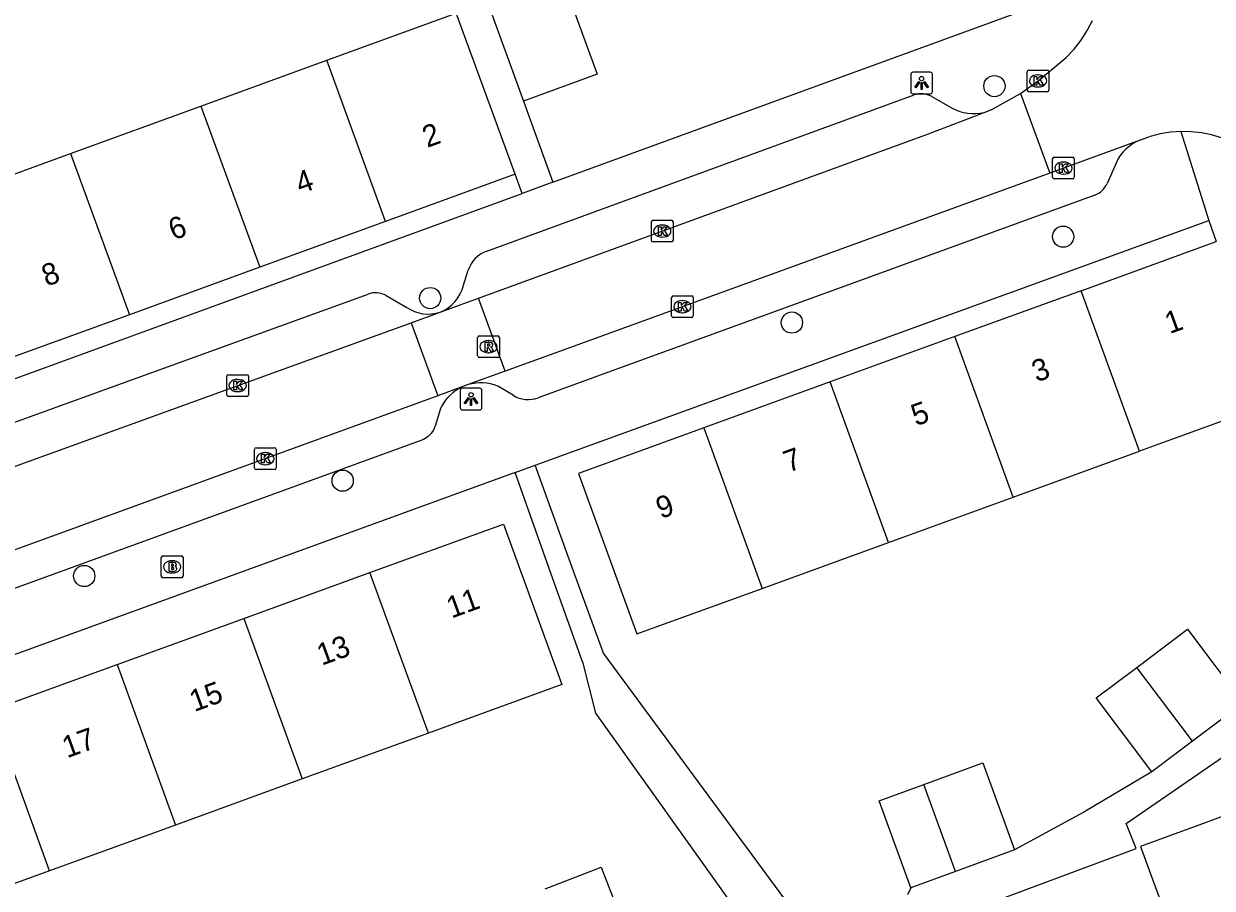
# Model space of a CAD drawing. Extents: x 159222 to 160346, y 381249 to 382166.
# Drawn here: x 159605.3 to 159660.1, y 381397.6 to 381437.5 of the extents above; entities that cross this region are included whole.
import ezdxf

# ---------------------------------------------------------------- set-up
doc = ezdxf.new("R2010")
doc.units = 0
for name, color, linetype in [('IMGEO_Boom', 7, 'Continuous'), ('IMGEO_Brandkraan', 7, 'Continuous'), ('IMGEO_Kolk', 7, 'Continuous'), ('IMGEO_Lichtpunt', 7, 'Continuous'), ('IMGEO_Pand', 7, 'Continuous'), ('IMGEO_Pand_nummerreeks', 7, 'Continuous'), ('IMGEO_Rijbaan_lokaal_open', 7, 'Continuous'), ('IMGEO_Rioolput', 7, 'Continuous'), ('IMGEO_Voetpad_open', 7, 'Continuous')]:
    doc.layers.add(name, color=color, linetype=linetype)

msp = doc.modelspace()

# ---------------------------------------------------------------- linework, layer by layer
at = {"layer": 'IMGEO_Boom'}
for centre in [(159650.085, 381434.629), (159653.252, 381427.689), (159624.075, 381424.855), (159640.749, 381423.725), (159620.038, 381416.439), (159608.128, 381412.043)]:
    msp.add_circle(centre, 0.489, dxfattribs=at)
at = {"layer": 'IMGEO_Brandkraan'}
for p, q in [((159611.679, 381412.038), (159611.679, 381412.89)), ((159611.754, 381412.964), (159612.606, 381412.964)), ((159612.167, 381412.744), (159612.192, 381412.744)), ((159612.68, 381412.89), (159612.68, 381412.038)), ((159612.19, 381412.184), (159612.165, 381412.184)), ((159612.606, 381411.964), (159611.754, 381411.964))]:
    msp.add_line(p, q, dxfattribs=at)
for points in [[(159611.679, 381412.038), (159611.679, 381412.89)], [(159611.754, 381412.964), (159612.606, 381412.964)], [(159612.68, 381412.89), (159612.68, 381412.038)], [(159612.027, 381412.664), (159612.027, 381412.264), (159612.24, 381412.264)], [(159612.258, 381412.664), (159612.027, 381412.664)], [(159612.206, 381412.583), (159612.152, 381412.583), (159612.152, 381412.507)], [(159612.152, 381412.507), (159612.205, 381412.507)], [(159612.214, 381412.431), (159612.152, 381412.431), (159612.152, 381412.35)], [(159612.152, 381412.35), (159612.214, 381412.35)], [(159612.606, 381411.964), (159611.754, 381411.964)]]:
    msp.add_lwpolyline(points, dxfattribs=at)
for centre, radius, start, end in [((159611.756, 381412.888), 0.0765, 91.552, 178.448), ((159611.756, 381412.888), 0.0765, 91.552, 178.448), ((159612.604, 381412.888), 0.0765, 1.552, 88.448), ((159612.604, 381412.888), 0.0765, 1.552, 88.448), ((159612.207, 381412.545), 0.0379, 267.8285, 90.9355), ((159612.215, 381412.39), 0.0404, 269.8759, 90.5077), ((159612.246, 381412.515), 0.251, 268.6676, 293.5347), ((159612.262, 381412.519), 0.145, 59.4692, 91.5367), ((159612.287, 381412.566), 0.0922, 285.5137, 58.1501), ((159612.292, 381412.374), 0.105, 301.3115, 78.989), ((159611.756, 381412.04), 0.0765, 181.552, 268.448), ((159611.756, 381412.04), 0.0765, 181.552, 268.448), ((159612.604, 381412.04), 0.0765, 271.552, 358.448), ((159612.604, 381412.04), 0.0765, 271.552, 358.448)]:
    msp.add_arc(centre, radius, start, end, dxfattribs=at)
for centre, major_axis, ratio, start_param, end_param in [((159612.166, 381412.464), (-0.387, 0.002), 0.722429, 4.712389, 7.853982), ((159612.191, 381412.464), (-0.39, 0.002), 0.717154, 1.570796, 4.712389)]:
    msp.add_ellipse(centre, major_axis=major_axis, ratio=ratio, start_param=start_param, end_param=end_param, dxfattribs=at)
at = {"layer": 'IMGEO_Kolk'}
for p, q in [((159651.596, 381434.442), (159651.596, 381435.294)), ((159651.671, 381435.368), (159652.523, 381435.368)), ((159652.597, 381435.294), (159652.597, 381434.442)), ((159652.084, 381435.148), (159652.109, 381435.148)), ((159652.523, 381434.368), (159651.671, 381434.368)), ((159652.107, 381434.588), (159652.082, 381434.588)), ((159652.766, 381430.424), (159652.766, 381431.276)), ((159652.841, 381431.35), (159653.693, 381431.35)), ((159653.254, 381431.13), (159653.279, 381431.13)), ((159653.767, 381431.276), (159653.767, 381430.424)), ((159653.693, 381430.35), (159652.841, 381430.35)), ((159653.277, 381430.57), (159653.252, 381430.57)), ((159634.273, 381427.518), (159634.273, 381428.37)), ((159634.348, 381428.444), (159635.2, 381428.444)), ((159634.761, 381428.224), (159634.786, 381428.224)), ((159635.274, 381428.37), (159635.274, 381427.518)), ((159634.784, 381427.664), (159634.759, 381427.664)), ((159635.2, 381427.444), (159634.348, 381427.444)), ((159635.202, 381424.032), (159635.202, 381424.884)), ((159635.277, 381424.958), (159636.129, 381424.958)), ((159636.203, 381424.884), (159636.203, 381424.032)), ((159635.69, 381424.738), (159635.715, 381424.738)), ((159636.129, 381423.958), (159635.277, 381423.958)), ((159635.713, 381424.178), (159635.688, 381424.178)), ((159614.699, 381420.398), (159614.699, 381421.25)), ((159614.774, 381421.324), (159615.626, 381421.324)), ((159615.187, 381421.104), (159615.212, 381421.104)), ((159615.7, 381421.25), (159615.7, 381420.398)), ((159615.21, 381420.544), (159615.185, 381420.544)), ((159615.626, 381420.324), (159614.774, 381420.324)), ((159615.974, 381417.027), (159615.974, 381417.879)), ((159616.049, 381417.953), (159616.901, 381417.953)), ((159616.462, 381417.733), (159616.487, 381417.733)), ((159616.975, 381417.879), (159616.975, 381417.027)), ((159616.485, 381417.173), (159616.46, 381417.173)), ((159616.901, 381416.953), (159616.049, 381416.953))]:
    msp.add_line(p, q, dxfattribs=at)
for points in [[(159651.596, 381434.442), (159651.596, 381435.294)], [(159651.671, 381435.368), (159652.523, 381435.368)], [(159652.597, 381435.294), (159652.597, 381434.442)], [(159651.917, 381435.068), (159652.04, 381435.068), (159652.04, 381434.917), (159652.17, 381435.068), (159652.334, 381435.068), (159652.188, 381434.917), (159652.341, 381434.668), (159652.189, 381434.668), (159652.104, 381434.832), (159652.04, 381434.765), (159652.04, 381434.668), (159651.917, 381434.668), (159651.917, 381435.068)], [(159652.523, 381434.368), (159651.671, 381434.368)], [(159652.766, 381430.424), (159652.766, 381431.276)], [(159652.841, 381431.35), (159653.693, 381431.35)], [(159653.087, 381431.05), (159653.21, 381431.05), (159653.21, 381430.899), (159653.34, 381431.05), (159653.504, 381431.05), (159653.358, 381430.899), (159653.511, 381430.65), (159653.359, 381430.65), (159653.274, 381430.814), (159653.21, 381430.747), (159653.21, 381430.65), (159653.087, 381430.65), (159653.087, 381431.05)], [(159653.767, 381431.276), (159653.767, 381430.424)], [(159653.693, 381430.35), (159652.841, 381430.35)], [(159634.273, 381427.518), (159634.273, 381428.37)], [(159634.348, 381428.444), (159635.2, 381428.444)], [(159634.594, 381428.144), (159634.717, 381428.144), (159634.717, 381427.993), (159634.847, 381428.144), (159635.011, 381428.144), (159634.865, 381427.993), (159635.018, 381427.744), (159634.866, 381427.744), (159634.781, 381427.908), (159634.717, 381427.841), (159634.717, 381427.744), (159634.594, 381427.744), (159634.594, 381428.144)], [(159635.274, 381428.37), (159635.274, 381427.518)], [(159635.2, 381427.444), (159634.348, 381427.444)], [(159635.202, 381424.032), (159635.202, 381424.884)], [(159635.277, 381424.958), (159636.129, 381424.958)], [(159636.203, 381424.884), (159636.203, 381424.032)], [(159635.523, 381424.658), (159635.646, 381424.658), (159635.646, 381424.507), (159635.776, 381424.658), (159635.94, 381424.658), (159635.794, 381424.507), (159635.947, 381424.258), (159635.795, 381424.258), (159635.71, 381424.422), (159635.646, 381424.355), (159635.646, 381424.258), (159635.523, 381424.258), (159635.523, 381424.658)], [(159636.129, 381423.958), (159635.277, 381423.958)], [(159614.699, 381420.398), (159614.699, 381421.25)], [(159614.774, 381421.324), (159615.626, 381421.324)], [(159615.02, 381421.024), (159615.143, 381421.024), (159615.143, 381420.873), (159615.273, 381421.024), (159615.437, 381421.024), (159615.291, 381420.873), (159615.444, 381420.624), (159615.292, 381420.624), (159615.207, 381420.788), (159615.143, 381420.721), (159615.143, 381420.624), (159615.02, 381420.624), (159615.02, 381421.024)], [(159615.7, 381421.25), (159615.7, 381420.398)], [(159615.626, 381420.324), (159614.774, 381420.324)], [(159615.974, 381417.027), (159615.974, 381417.879)], [(159616.049, 381417.953), (159616.901, 381417.953)], [(159616.975, 381417.879), (159616.975, 381417.027)], [(159616.295, 381417.653), (159616.418, 381417.653), (159616.418, 381417.502), (159616.548, 381417.653), (159616.712, 381417.653), (159616.566, 381417.502), (159616.719, 381417.253), (159616.567, 381417.253), (159616.482, 381417.417), (159616.418, 381417.35), (159616.418, 381417.253), (159616.295, 381417.253), (159616.295, 381417.653)], [(159616.901, 381416.953), (159616.049, 381416.953)]]:
    msp.add_lwpolyline(points, dxfattribs=at)
for centre, start, end in [((159651.673, 381435.292), 91.552, 178.448), ((159651.673, 381435.292), 91.552, 178.448), ((159652.521, 381435.292), 1.552, 88.448), ((159652.521, 381435.292), 1.552, 88.448), ((159651.673, 381434.444), 181.552, 268.448), ((159651.673, 381434.444), 181.552, 268.448), ((159652.521, 381434.444), 271.552, 358.448), ((159652.521, 381434.444), 271.552, 358.448), ((159652.843, 381431.274), 91.552, 178.448), ((159652.843, 381431.274), 91.552, 178.448), ((159653.691, 381431.274), 1.552, 88.448), ((159653.691, 381431.274), 1.552, 88.448), ((159652.843, 381430.426), 181.552, 268.448), ((159652.843, 381430.426), 181.552, 268.448), ((159653.691, 381430.426), 271.552, 358.448), ((159653.691, 381430.426), 271.552, 358.448), ((159634.35, 381428.368), 91.552, 178.448), ((159634.35, 381428.368), 91.552, 178.448), ((159635.198, 381428.368), 1.552, 88.448), ((159635.198, 381428.368), 1.552, 88.448), ((159634.35, 381427.52), 181.552, 268.448), ((159634.35, 381427.52), 181.552, 268.448), ((159635.198, 381427.52), 271.552, 358.448), ((159635.198, 381427.52), 271.552, 358.448), ((159635.279, 381424.882), 91.552, 178.448), ((159635.279, 381424.882), 91.552, 178.448), ((159636.127, 381424.882), 1.552, 88.448), ((159636.127, 381424.882), 1.552, 88.448), ((159635.279, 381424.034), 181.552, 268.448), ((159635.279, 381424.034), 181.552, 268.448), ((159636.127, 381424.034), 271.552, 358.448), ((159636.127, 381424.034), 271.552, 358.448), ((159614.776, 381421.248), 91.552, 178.448), ((159614.776, 381421.248), 91.552, 178.448), ((159615.624, 381421.248), 1.552, 88.448), ((159615.624, 381421.248), 1.552, 88.448), ((159614.776, 381420.4), 181.552, 268.448), ((159614.776, 381420.4), 181.552, 268.448), ((159615.624, 381420.4), 271.552, 358.448), ((159615.624, 381420.4), 271.552, 358.448), ((159616.051, 381417.877), 91.552, 178.448), ((159616.051, 381417.877), 91.552, 178.448), ((159616.899, 381417.877), 1.552, 88.448), ((159616.899, 381417.877), 1.552, 88.448), ((159616.051, 381417.029), 181.552, 268.448), ((159616.051, 381417.029), 181.552, 268.448), ((159616.899, 381417.029), 271.552, 358.448), ((159616.899, 381417.029), 271.552, 358.448)]:
    msp.add_arc(centre, 0.0765, start, end, dxfattribs=at)
for centre, major_axis, ratio, start_param, end_param in [((159652.083, 381434.868), (-0.387, 0.002), 0.722429, 4.712389, 7.853982), ((159652.108, 381434.868), (-0.39, 0.002), 0.717154, 1.570796, 4.712389), ((159653.253, 381430.85), (-0.387, 0.002), 0.722429, 4.712389, 7.853982), ((159653.278, 381430.85), (-0.39, 0.002), 0.717154, 1.570796, 4.712389), ((159634.76, 381427.944), (-0.387, 0.002), 0.722429, 4.712389, 7.853982), ((159634.785, 381427.944), (-0.39, 0.002), 0.717154, 1.570796, 4.712389), ((159635.689, 381424.458), (-0.387, 0.002), 0.722429, 4.712389, 7.853982), ((159635.714, 381424.458), (-0.39, 0.002), 0.717154, 1.570796, 4.712389), ((159615.186, 381420.824), (-0.387, 0.002), 0.722429, 4.712389, 7.853982), ((159615.211, 381420.824), (-0.39, 0.002), 0.717154, 1.570796, 4.712389), ((159616.461, 381417.453), (-0.387, 0.002), 0.722429, 4.712389, 7.853982), ((159616.486, 381417.453), (-0.39, 0.002), 0.717154, 1.570796, 4.712389)]:
    msp.add_ellipse(centre, major_axis=major_axis, ratio=ratio, start_param=start_param, end_param=end_param, dxfattribs=at)
at = {"layer": 'IMGEO_Lichtpunt'}
for p, q in [((159647.132, 381435.271), (159646.324, 381435.271)), ((159647.132, 381435.271), (159646.324, 381435.271)), ((159646.23, 381435.176), (159646.23, 381434.369)), ((159646.23, 381435.176), (159646.23, 381434.369)), ((159647.226, 381434.369), (159647.226, 381435.176)), ((159647.226, 381434.369), (159647.226, 381435.176)), ((159646.324, 381434.275), (159647.132, 381434.275)), ((159646.324, 381434.275), (159647.132, 381434.275)), ((159625.46, 381420.602), (159625.46, 381419.795)), ((159625.46, 381420.602), (159625.46, 381419.795)), ((159626.362, 381420.697), (159625.554, 381420.697)), ((159626.362, 381420.697), (159625.554, 381420.697)), ((159626.456, 381419.795), (159626.456, 381420.602)), ((159626.456, 381419.795), (159626.456, 381420.602)), ((159625.554, 381419.701), (159626.362, 381419.701)), ((159625.554, 381419.701), (159626.362, 381419.701))]:
    msp.add_line(p, q, dxfattribs=at)
for points in [[(159646.604, 381434.84), (159646.643, 381434.812), (159646.455, 381434.55), (159646.417, 381434.577), (159646.604, 381434.84)], [(159646.706, 381434.792), (159646.753, 381434.792), (159646.753, 381434.47), (159646.706, 381434.47), (159646.706, 381434.792)], [(159646.816, 381434.812), (159646.854, 381434.839), (159647.041, 381434.577), (159647.002, 381434.549), (159646.816, 381434.812)], [(159625.834, 381420.266), (159625.873, 381420.238), (159625.685, 381419.976), (159625.647, 381420.003), (159625.834, 381420.266)], [(159625.936, 381420.218), (159625.983, 381420.218), (159625.983, 381419.896), (159625.936, 381419.896), (159625.936, 381420.218)], [(159626.046, 381420.238), (159626.084, 381420.265), (159626.271, 381420.003), (159626.232, 381419.975), (159626.046, 381420.238)]]:
    msp.add_lwpolyline(points, dxfattribs=at)
for centre in [(159646.729, 381434.974), (159625.959, 381420.4)]:
    msp.add_circle(centre, 0.0994, dxfattribs=at)
for centre, start, end in [((159646.324, 381435.176), 90, 180), ((159646.324, 381435.176), 90, 180), ((159647.132, 381435.176), 0, 90), ((159647.132, 381435.176), 0, 90), ((159646.324, 381434.369), 180, 270), ((159646.324, 381434.369), 180, 270), ((159647.132, 381434.369), 270, 0), ((159647.132, 381434.369), 270, 360), ((159625.554, 381420.602), 90, 180), ((159625.554, 381420.602), 90, 180), ((159626.362, 381420.602), 0, 90), ((159626.362, 381420.602), 0, 90), ((159625.554, 381419.795), 180, 270), ((159625.554, 381419.795), 180, 270), ((159626.362, 381419.795), 270, 0), ((159626.362, 381419.795), 270, 360)]:
    msp.add_arc(centre, 0.0946, start, end, dxfattribs=at)
at = {"layer": 'IMGEO_Pand'}
for points in [[(159626.725, 381438.45), (159630.125, 381439.69), (159631.77, 381435.176), (159628.37, 381433.937)], [(159619.309, 381435.822), (159625.278, 381437.998)], [(159627.986, 381430.569), (159626.274, 381435.267), (159625.278, 381437.998)], [(159626.725, 381438.45), (159628.37, 381433.937)], [(159613.506, 381433.706), (159619.309, 381435.822)], [(159622.018, 381428.393), (159619.309, 381435.822)], [(159607.501, 381431.517), (159613.506, 381433.706)], [(159613.506, 381433.706), (159616.215, 381426.278)], [(159601.858, 381429.46), (159607.501, 381431.517)], [(159607.501, 381431.517), (159610.21, 381424.089)], [(159627.986, 381430.569), (159622.018, 381428.393)], [(159622.018, 381428.393), (159616.215, 381426.278)], [(159654.081, 381425.197), (159660.305, 381427.46)], [(159616.215, 381426.278), (159610.21, 381424.089)], [(159654.081, 381425.197), (159648.254, 381423.079)], [(159656.772, 381417.793), (159654.081, 381425.197)], [(159610.21, 381424.089), (159604.567, 381422.032)], [(159648.254, 381423.079), (159642.509, 381420.991)], [(159650.946, 381415.675), (159648.254, 381423.079)], [(159642.509, 381420.991), (159636.683, 381418.872)], [(159645.201, 381413.587), (159642.509, 381420.991)], [(159662.997, 381420.056), (159658.298, 381418.348), (159656.772, 381417.793)], [(159636.683, 381418.872), (159630.905, 381416.772), (159632.613, 381412.073), (159633.596, 381409.368), (159639.374, 381411.469)], [(159636.683, 381418.872), (159639.374, 381411.469)], [(159650.946, 381415.675), (159656.772, 381417.793)], [(159645.201, 381413.587), (159650.946, 381415.675)], [(159621.299, 381412.201), (159627.45, 381414.437), (159629.159, 381409.739), (159630.142, 381407.035), (159623.99, 381404.798)], [(159639.374, 381411.469), (159645.201, 381413.587)], [(159615.485, 381410.087), (159621.299, 381412.201)], [(159623.99, 381404.798), (159621.299, 381412.201)], [(159609.644, 381407.964), (159615.485, 381410.087)], [(159615.485, 381410.087), (159618.176, 381402.685)], [(159656.644, 381407.827), (159658.991, 381409.59), (159661.552, 381406.18)], [(159603.835, 381405.852), (159609.644, 381407.964)], [(159609.644, 381407.964), (159612.335, 381400.561)], [(159657.335, 381403.012), (159654.773, 381406.421), (159656.644, 381407.827)], [(159659.215, 381404.424), (159656.644, 381407.827)], [(159661.552, 381406.18), (159659.215, 381404.424)], [(159606.526, 381398.449), (159603.835, 381405.852)], [(159623.99, 381404.798), (159618.176, 381402.685)], [(159659.215, 381404.424), (159657.335, 381403.012)], [(159646.829, 381402.425), (159649.556, 381403.42), (159651.017, 381399.415)], [(159670.828, 381398.23), (159669.904, 381400.754), (159668.351, 381400.186), (159667.19, 381403.357), (159662.471, 381401.643), (159659.05, 381400.391), (159656.814, 381399.573), (159658.904, 381393.862), (159661.14, 381394.681)], [(159618.176, 381402.685), (159612.335, 381400.561)], [(159646.229, 381397.668), (159644.767, 381401.673), (159646.829, 381402.425)], [(159648.288, 381398.419), (159646.829, 381402.425)], [(159612.335, 381400.561), (159606.526, 381398.449)], [(159651.017, 381399.415), (159648.288, 381398.419)], [(159629.368, 381397.623), (159631.949, 381398.621), (159633.519, 381394.563)], [(159606.526, 381398.449), (159600.648, 381396.312)], [(159648.288, 381398.419), (159646.229, 381397.668)]]:
    msp.add_lwpolyline(points, dxfattribs=at)
at = {"layer": 'IMGEO_Rijbaan_lokaal_open'}
for points in [[(159651.291, 381434.293), (159652.095, 381434.865), (159653.397, 381435.95), (159653.755, 381436.334), (159654.077, 381436.749), (159654.361, 381437.191), (159654.605, 381437.657)], [(159649.608, 381433.413), (159649.962, 381433.555), (159651.291, 381434.293)], [(159651.291, 381434.293), (159652.632, 381430.621)], [(159626.306, 381424.852), (159647.045, 381432.423), (159649.608, 381433.413)], [(159658.676, 381432.534), (159658.2, 381432.499), (159657.73, 381432.422), (159657.268, 381432.304), (159657.185, 381432.278), (159656.809, 381432.141)], [(159663.908, 381429.84), (159663.482, 381430.34), (159663.013, 381430.8), (159662.505, 381431.216), (159662.429, 381431.272), (159661.945, 381431.597), (159661.433, 381431.877), (159660.995, 381432.073), (159660.551, 381432.248), (159660.094, 381432.382), (159659.626, 381432.475), (159659.152, 381432.525), (159658.676, 381432.534)], [(159656.809, 381432.141), (159652.632, 381430.621)], [(159652.632, 381430.621), (159631.043, 381422.764), (159627.533, 381421.485)], [(159624.535, 381424.208), (159625.459, 381424.543), (159626.306, 381424.852)], [(159627.533, 381421.485), (159626.306, 381424.852)], [(159589.053, 381411.283), (159601.832, 381415.978), (159623.195, 381423.722)], [(159623.195, 381423.722), (159624.535, 381424.208)], [(159623.195, 381423.722), (159624.423, 381420.352)], [(159627.533, 381421.485), (159625.829, 381420.864)], [(159625.581, 381420.773), (159624.423, 381420.352)], [(159625.829, 381420.864), (159625.581, 381420.773)], [(159624.423, 381420.352), (159602.469, 381412.351), (159590.271, 381407.929)]]:
    msp.add_lwpolyline(points, dxfattribs=at)
at = {"layer": 'IMGEO_Rioolput'}
for p, q in [((159626.263, 381422.187), (159626.263, 381423.039)), ((159626.338, 381423.113), (159627.19, 381423.113)), ((159626.751, 381422.893), (159626.776, 381422.893)), ((159627.264, 381423.039), (159627.264, 381422.187)), ((159627.19, 381422.113), (159626.338, 381422.113)), ((159626.774, 381422.333), (159626.749, 381422.333))]:
    msp.add_line(p, q, dxfattribs=at)
for points in [[(159626.263, 381422.187), (159626.263, 381423.039)], [(159626.338, 381423.113), (159627.19, 381423.113)], [(159626.852, 381422.811), (159626.6, 381422.813), (159626.6, 381422.413)], [(159626.778, 381422.732), (159626.724, 381422.732), (159626.724, 381422.651)], [(159626.724, 381422.651), (159626.776, 381422.651)], [(159627.264, 381423.039), (159627.264, 381422.187)], [(159627.19, 381422.113), (159626.338, 381422.113)], [(159626.6, 381422.413), (159626.724, 381422.413), (159626.724, 381422.575), (159626.735, 381422.575)], [(159626.782, 381422.546), (159626.853, 381422.413), (159626.993, 381422.413), (159626.928, 381422.539)]]:
    msp.add_lwpolyline(points, dxfattribs=at)
for centre, radius, start, end in [((159626.34, 381423.037), 0.0765, 91.552, 178.448), ((159626.34, 381423.037), 0.0765, 91.552, 178.448), ((159626.76, 381422.84), 0.19, 274.7715, 282.9687), ((159626.784, 381422.636), 0.0964, 77.0061, 93.1865), ((159626.798, 381422.693), 0.0378, 276.6634, 79.6772), ((159626.851, 381422.701), 0.109, 350.3612, 89.416), ((159626.849, 381422.701), 0.112, 277.5842, 350.9817), ((159627.188, 381423.037), 0.0765, 1.552, 88.448), ((159627.188, 381423.037), 0.0765, 1.552, 88.448), ((159626.34, 381422.189), 0.0765, 181.552, 268.448), ((159626.34, 381422.189), 0.0765, 181.552, 268.448), ((159626.734, 381422.522), 0.0533, 26.0293, 88.6989), ((159626.833, 381422.486), 0.108, 29.5134, 73.7905), ((159627.188, 381422.189), 0.0765, 271.552, 358.448), ((159627.188, 381422.189), 0.0765, 271.552, 358.448)]:
    msp.add_arc(centre, radius, start, end, dxfattribs=at)
for centre, major_axis, ratio, start_param, end_param in [((159626.75, 381422.613), (-0.387, 0.002), 0.722429, 4.712389, 7.853982), ((159626.775, 381422.613), (-0.39, 0.002), 0.717154, 1.570796, 4.712389)]:
    msp.add_ellipse(centre, major_axis=major_axis, ratio=ratio, start_param=start_param, end_param=end_param, dxfattribs=at)
at = {"layer": 'IMGEO_Voetpad_open'}
for points in [[(159629.734, 381430.203), (159651.161, 381438.028), (159651.846, 381438.493), (159652.201, 381439.407), (159652.095, 381440.154), (159651.623, 381441.001)], [(159626.679, 381427.026), (159646.388, 381434.221)], [(159647.192, 381434.146), (159648.139, 381433.618)], [(159628.37, 381433.937), (159629.734, 381430.203)], [(159658.676, 381432.534), (159659.964, 381428.438)], [(159655.691, 381431.076), (159655.28, 381430.14)], [(159628.31, 381429.683), (159627.986, 381430.569)], [(159629.734, 381430.203), (159628.31, 381429.683)], [(159555.602, 381403.13), (159562.375, 381405.604), (159569.991, 381408.385), (159628.31, 381429.683)], [(159654.707, 381429.602), (159631.614, 381421.197), (159629.049, 381420.262)], [(159628.912, 381417.147), (159659.964, 381428.438)], [(159659.964, 381428.438), (159660.305, 381427.46)], [(159625.604, 381425.447), (159625.826, 381426.138)], [(159589.7, 381413.56), (159601.176, 381417.776), (159621.211, 381425.039)], [(159622.046, 381424.968), (159622.997, 381424.428)], [(159625.581, 381420.773), (159625.416, 381420.692), (159625.259, 381420.596), (159625.112, 381420.487), (159624.974, 381420.365), (159624.849, 381420.232), (159624.735, 381420.087), (159624.635, 381419.934), (159624.548, 381419.769), (159624.3, 381418.956), (159624.292, 381418.93), (159624.259, 381418.846), (159624.22, 381418.766), (159624.173, 381418.689), (159624.119, 381418.617), (159624.06, 381418.55), (159623.994, 381418.489), (159623.924, 381418.433), (159623.848, 381418.385), (159623.769, 381418.343), (159623.686, 381418.308), (159603.039, 381410.784)], [(159627.892, 381420.372), (159627.195, 381420.79)], [(159627.985, 381416.81), (159628.912, 381417.147)], [(159641.552, 381395.626), (159632.064, 381408.478), (159630.688, 381412.263), (159628.912, 381417.147)], [(159627.985, 381416.81), (159591.614, 381403.586), (159587.766, 381402.031), (159558.393, 381391.348), (159558.696, 381390.481)], [(159633.519, 381394.563), (159638.339, 381396.427), (159631.712, 381405.711), (159631.123, 381408.017), (159631.084, 381408.128), (159629.732, 381411.915), (159627.985, 381416.81)], [(159648.337, 381395.135), (159647.926, 381396.235), (159656.619, 381399.483), (159656.162, 381400.633), (159669.768, 381410.008)], [(159657.335, 381403.012), (159654.201, 381401.146), (159651.017, 381399.415)], [(159646.229, 381397.668), (159646.076, 381397.334)]]:
    msp.add_lwpolyline(points, dxfattribs=at)
for centre, radius, start, end in [((159646.704, 381433.258), 1.014, 61.1971, 108.1443), ((159649.138, 381435.408), 2.05, 240.8429, 283.2684), ((159657.52, 381430.275), 1.997, 110.8678, 156.3506), ((159654.369, 381430.536), 0.994, 289.9028, 336.4884), ((159627.155, 381425.715), 1.395, 109.9596, 162.3438), ((159623.892, 381425.843), 1.757, 291.4605, 346.9647), ((159621.552, 381424.107), 0.992, 60.1629, 110.1167), ((159623.985, 381425.852), 1.733, 235.2296, 288.4893), ((159626.407, 381418.892), 2.055, 67.4609, 106.3374), ((159628.586, 381421.529), 1.349, 239.0496, 290.0884)]:
    msp.add_arc(centre, radius, start, end, dxfattribs=at)

# ---------------------------------------------------------------- texts
at = {"layer": 'IMGEO_Pand_nummerreeks'}
for s, rotation, p in [('2', 20.0296, (159623.936, 381431.775)), ('4', 20.0296, (159618.088, 381429.643)), ('6', 20.0296, (159612.237, 381427.51)), ('8', 20.0296, (159606.39, 381425.378)), ('1', 19.9781, (159658.162, 381423.191)), ('3', 19.9781, (159652.029, 381420.962)), ('5', 19.9781, (159646.467, 381418.94)), ('7', 19.9781, (159640.587, 381416.802)), ('9', 19.9781, (159634.707, 381414.664)), ('11', 19.9788, (159625.052, 381410.075)), ('13', 19.9788, (159619.074, 381407.902)), ('15', 19.9788, (159613.204, 381405.768)), ('17', 19.9788, (159607.334, 381403.634))]:
    msp.add_text(s, height=1, rotation=rotation, dxfattribs=at).set_placement(p)

doc.saveas('drawing.dxf')
